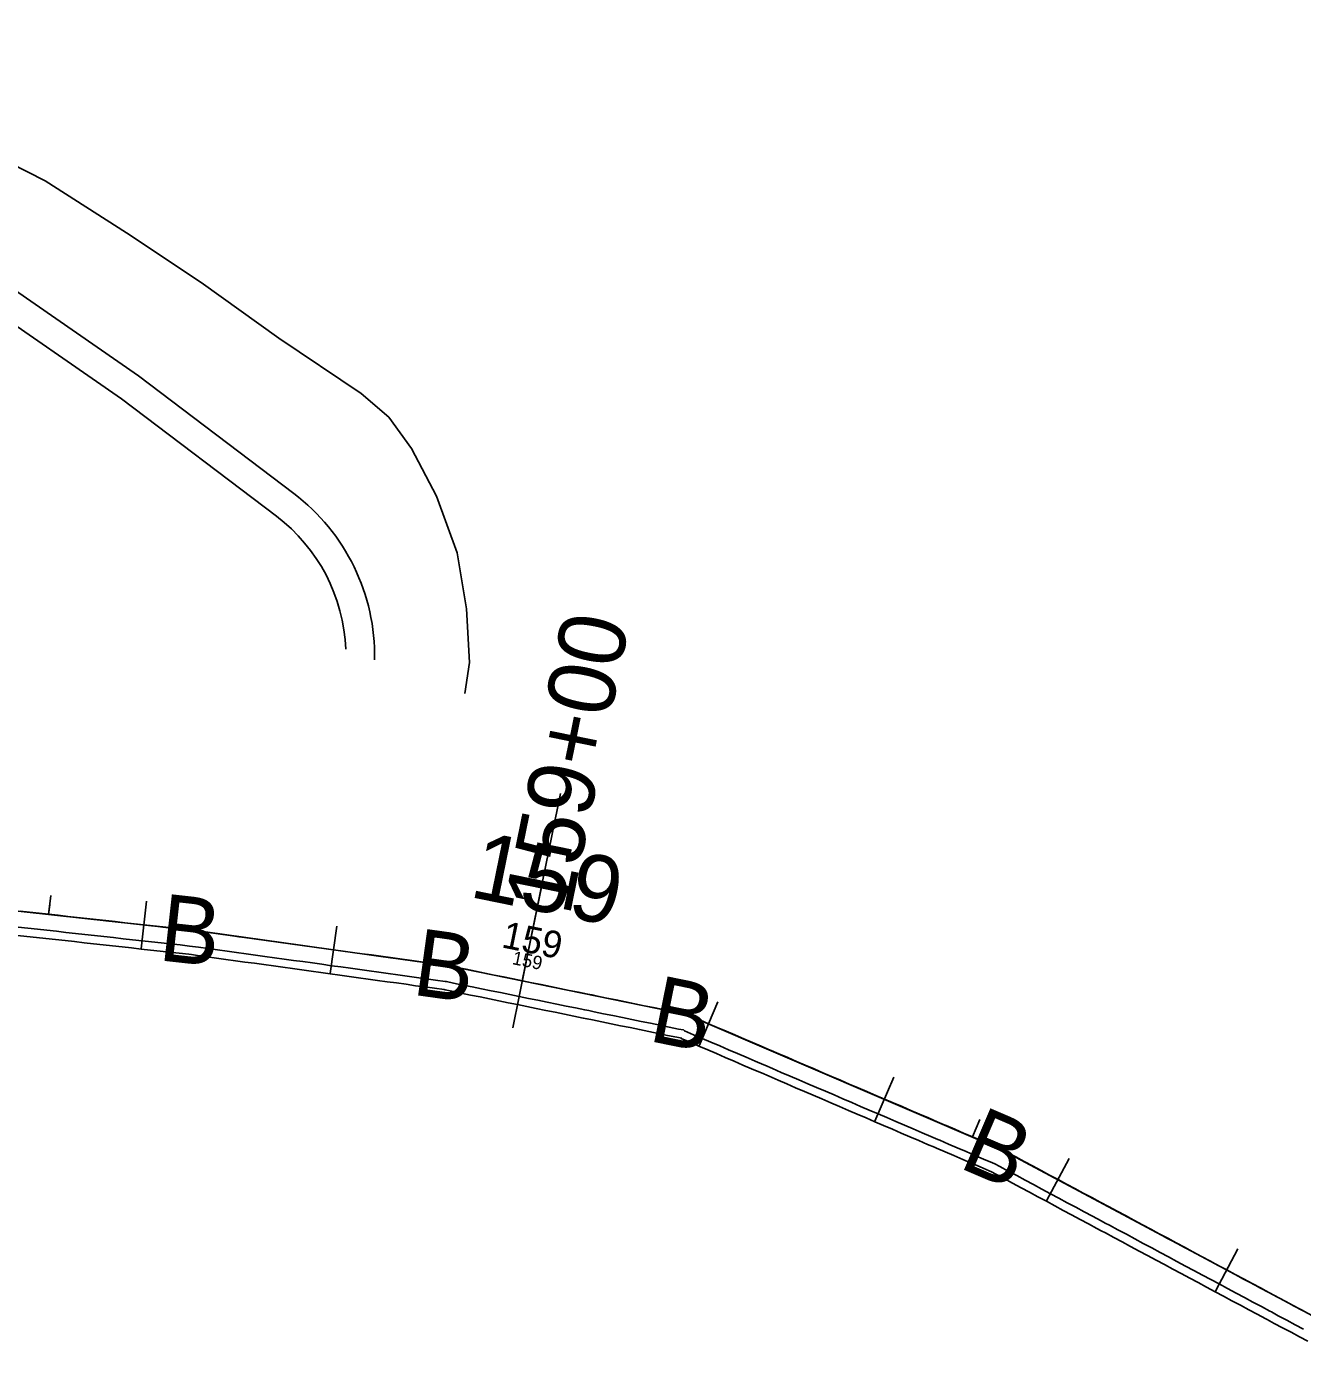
# Model space of a CAD drawing. Extents: x 1823824 to 1861612, y 706975 to 726130.
# Drawn here: x 1825799.9 to 1825933.2, y 715486.9 to 715624.8 of the extents above; entities that cross this region are included whole.
import ezdxf

# ---------------------------------------------------------------- set-up
doc = ezdxf.new("R2010")
doc.units = 0
for name, color, linetype in [('DR_X_Flood_Boundary', 7, 'Continuous'), ('GE_X_CL_10', 7, 'Continuous'), ('GE_X_CL_100', 7, 'Continuous'), ('GE_X_CL_20', 7, 'Continuous'), ('GE_X_CL_200', 7, 'Continuous'), ('GE_X_CL_50', 7, 'Continuous'), ('SC_Scratch1', 7, 'Continuous'), ('SC_Scratch3', 7, 'Continuous'), ('SC_Scratch5', 7, 'Continuous'), ('SC_Scratch6', 7, 'Continuous')]:
    doc.layers.add(name, color=color, linetype=linetype)

msp = doc.modelspace()

# ---------------------------------------------------------------- linework, layer by layer
at = {"layer": 'DR_X_Flood_Boundary'}
for p, q in [((1825794.14, 715532.96), (1825817.43, 715530.38)), ((1825817.43, 715530.38), (1825844.02, 715526.69)), ((1825844.02, 715526.69), (1825868.88, 715521.61)), ((1825868.88, 715521.61), (1825901.75, 715507.52)), ((1825901.75, 715507.52), (1825940.26, 715486.91))]:
    msp.add_line(p, q, dxfattribs=at)
at = {"layer": 'GE_X_CL_10'}
for p, q in [((1825802.23, 715532.06), (1825802.34, 715533.05)), ((1825851.72, 715525.12), (1825851.92, 715526.1)), ((1825898.74, 715508.81), (1825899.13, 715509.73))]:
    msp.add_line(p, q, dxfattribs=at)
at = {"layer": 'GE_X_CL_100'}
msp.add_line((1825851.72, 715525.12), (1825853.72, 715534.91), dxfattribs=at)
at = {"layer": 'GE_X_CL_20'}
for p, q in [((1825802.23, 715532.06), (1825802.45, 715534.05)), ((1825851.72, 715525.12), (1825852.12, 715527.08)), ((1825898.74, 715508.81), (1825899.53, 715510.65))]:
    msp.add_line(p, q, dxfattribs=at)
at = {"layer": 'GE_X_CL_200'}
msp.add_line((1825851.72, 715525.12), (1825855.72, 715544.71), dxfattribs=at)
at = {"layer": 'GE_X_CL_50'}
msp.add_line((1825851.72, 715525.12), (1825852.72, 715530.02), dxfattribs=at)
at = {"layer": 'SC_Scratch1'}
for points in [[(1825771.61, 715624.85), (1825777.97, 715621.23), (1825782.31, 715619.01), (1825786.84, 715616.63), (1825791.22, 715614.26), (1825796.17, 715611.62), (1825801.88, 715608.7)], [(1825801.88, 715608.7), (1825810.36, 715603.27), (1825818.18, 715598.09), (1825826.27, 715592.29), (1825834.88, 715586.48)], [(1825796.48, 715598.82), (1825811.61, 715588.35), (1825827.84, 715576.05)], [(1825794.94, 715596.24), (1825809.85, 715585.92), (1825826.03, 715573.66)], [(1825834.88, 715586.48), (1825837.77, 715584.01), (1825840.15, 715580.75), (1825840.15, 715580.75)], [(1825840.15, 715580.75), (1825842.76, 715575.78), (1825844.92, 715569.84), (1825845.89, 715564.01), (1825846.21, 715558.39), (1825845.73, 715555.13)]]:
    msp.add_lwpolyline(points, dxfattribs=at)
for radius, start in [(21.34, 358.9869), (18.34, 2.252)]:
    msp.add_arc((1825814.95, 715559.05), radius, start, 52.8446, dxfattribs=at)
at = {"layer": 'SC_Scratch3'}
for points in [[(1825799.25, 715532.41), (1825800.24, 715532.3), (1825801.24, 715532.19), (1825802.23, 715532.08), (1825803.22, 715531.97), (1825804.22, 715531.86), (1825805.21, 715531.75), (1825806.21, 715531.64), (1825807.2, 715531.53), (1825808.19, 715531.42), (1825809.19, 715531.31), (1825810.18, 715531.2), (1825811.18, 715531.09), (1825812.17, 715530.98), (1825813.16, 715530.87), (1825814.16, 715530.76), (1825815.15, 715530.65), (1825816.15, 715530.54), (1825817.14, 715530.43), (1825817.43, 715530.4), (1825818.13, 715530.3), (1825819.12, 715530.16), (1825820.11, 715530.03), (1825821.1, 715529.89), (1825822.09, 715529.75), (1825823.08, 715529.61), (1825824.07, 715529.48), (1825825.07, 715529.34), (1825826.06, 715529.2), (1825827.05, 715529.06)], [(1825804.22, 715531.85), (1825803.22, 715531.96), (1825802.23, 715532.07), (1825801.24, 715532.18), (1825800.24, 715532.29), (1825799.25, 715532.4)], [(1825895.8, 715510.08), (1825895.07, 715510.4), (1825894.15, 715510.79), (1825893.23, 715511.18), (1825892.31, 715511.58), (1825891.39, 715511.97), (1825890.47, 715512.37), (1825889.55, 715512.76), (1825888.63, 715513.15), (1825887.71, 715513.55), (1825886.79, 715513.94), (1825885.88, 715514.34), (1825884.96, 715514.73), (1825884.04, 715515.12), (1825883.12, 715515.52), (1825882.2, 715515.91), (1825881.28, 715516.31), (1825880.36, 715516.7), (1825879.44, 715517.09), (1825878.52, 715517.49), (1825877.71, 715517.84), (1825877.6, 715517.88), (1825876.69, 715518.28), (1825875.77, 715518.67), (1825874.85, 715519.07), (1825873.93, 715519.46), (1825873.01, 715519.85), (1825872.09, 715520.25), (1825871.17, 715520.64), (1825870.25, 715521.04), (1825869.33, 715521.43), (1825868.88, 715521.62), (1825868.38, 715521.73), (1825867.4, 715521.93), (1825866.42, 715522.13), (1825865.44, 715522.33), (1825864.46, 715522.53), (1825863.48, 715522.73), (1825862.5, 715522.93), (1825861.52, 715523.13), (1825860.54, 715523.33), (1825859.56, 715523.53), (1825858.99, 715523.64), (1825858.58, 715523.73), (1825857.6, 715523.93), (1825856.62, 715524.13), (1825855.64, 715524.33), (1825854.66, 715524.53), (1825853.68, 715524.73), (1825852.7, 715524.93), (1825851.72, 715525.13), (1825850.74, 715525.33), (1825849.76, 715525.53), (1825848.78, 715525.73), (1825847.8, 715525.93), (1825846.83, 715526.13), (1825845.85, 715526.33), (1825844.87, 715526.53), (1825844.02, 715526.7), (1825843.88, 715526.72), (1825842.89, 715526.86), (1825841.9, 715526.99), (1825840.91, 715527.13), (1825839.92, 715527.27), (1825838.93, 715527.41), (1825837.94, 715527.54), (1825836.95, 715527.68), (1825835.96, 715527.82), (1825834.97, 715527.96), (1825833.98, 715528.09), (1825832.99, 715528.23), (1825832, 715528.37), (1825831.01, 715528.51), (1825830.02, 715528.64), (1825829.03, 715528.78), (1825828.04, 715528.92), (1825827.05, 715529.06), (1825826.05, 715529.19), (1825825.06, 715529.33), (1825824.07, 715529.47), (1825823.08, 715529.61), (1825822.09, 715529.74), (1825821.1, 715529.88), (1825820.11, 715530.02), (1825819.12, 715530.16), (1825818.13, 715530.29), (1825817.43, 715530.39), (1825817.14, 715530.42), (1825816.14, 715530.53), (1825815.15, 715530.64), (1825814.16, 715530.75), (1825813.16, 715530.86), (1825812.17, 715530.97), (1825811.18, 715531.08), (1825810.18, 715531.19), (1825809.19, 715531.3), (1825808.19, 715531.41), (1825807.2, 715531.52), (1825806.21, 715531.63), (1825805.21, 715531.74), (1825804.22, 715531.85)], [(1825799.06, 715530.74), (1825800.06, 715530.63), (1825801.05, 715530.52), (1825802.05, 715530.41), (1825803.04, 715530.3), (1825804.03, 715530.19), (1825805.03, 715530.08), (1825806.02, 715529.97), (1825807.02, 715529.86), (1825808.01, 715529.75), (1825809, 715529.64), (1825810, 715529.53), (1825810.99, 715529.42), (1825811.99, 715529.31), (1825812.98, 715529.2), (1825813.97, 715529.09), (1825814.97, 715528.98), (1825815.96, 715528.87), (1825816.96, 715528.76), (1825817.25, 715528.73), (1825817.9, 715528.64), (1825818.89, 715528.5), (1825819.88, 715528.36), (1825820.87, 715528.23), (1825821.86, 715528.09), (1825822.85, 715527.95), (1825823.84, 715527.81), (1825824.83, 715527.68), (1825825.83, 715527.54), (1825826.82, 715527.4)], [(1825803.94, 715529.33), (1825802.94, 715529.43), (1825801.95, 715529.54), (1825800.96, 715529.65), (1825799.96, 715529.76), (1825798.97, 715529.86)], [(1825894.79, 715507.73), (1825894.06, 715508.04), (1825893.14, 715508.44), (1825892.22, 715508.83), (1825891.3, 715509.22), (1825890.38, 715509.62), (1825889.46, 715510.02), (1825888.54, 715510.41), (1825887.63, 715510.81), (1825886.71, 715511.2), (1825885.79, 715511.59), (1825884.87, 715511.99), (1825883.95, 715512.38), (1825883.03, 715512.78), (1825882.11, 715513.17), (1825881.19, 715513.57), (1825880.27, 715513.96), (1825879.36, 715514.36), (1825878.44, 715514.75), (1825877.52, 715515.15), (1825876.7, 715515.5), (1825876.6, 715515.54), (1825875.68, 715515.94), (1825874.76, 715516.33), (1825873.84, 715516.73), (1825872.92, 715517.12), (1825872.01, 715517.52), (1825871.09, 715517.91), (1825870.17, 715518.3), (1825869.25, 715518.7), (1825868.33, 715519.09), (1825868.37, 715519.13), (1825867.87, 715519.23), (1825866.89, 715519.43), (1825865.91, 715519.63), (1825864.93, 715519.83), (1825863.95, 715520.03), (1825862.97, 715520.24), (1825861.99, 715520.44), (1825861.01, 715520.64), (1825860.03, 715520.84), (1825859.05, 715521.04), (1825858.49, 715521.15), (1825858.08, 715521.24), (1825857.1, 715521.44), (1825856.12, 715521.64), (1825855.14, 715521.84), (1825854.16, 715522.04), (1825853.18, 715522.24), (1825852.2, 715522.44), (1825851.22, 715522.64), (1825850.24, 715522.84), (1825849.26, 715523.04), (1825848.28, 715523.24), (1825847.3, 715523.44), (1825846.32, 715523.64), (1825845.34, 715523.84), (1825844.36, 715524.04), (1825843.67, 715524.19), (1825843.54, 715524.21), (1825842.55, 715524.35), (1825841.55, 715524.49), (1825840.56, 715524.62), (1825839.57, 715524.76), (1825838.58, 715524.9), (1825837.59, 715525.03), (1825836.6, 715525.17), (1825835.61, 715525.31), (1825834.62, 715525.44), (1825833.63, 715525.58), (1825832.64, 715525.72), (1825831.65, 715525.85), (1825830.66, 715525.99), (1825829.67, 715526.13), (1825828.68, 715526.27), (1825827.69, 715526.4), (1825826.7, 715526.54), (1825825.71, 715526.68), (1825824.72, 715526.82), (1825823.72, 715526.96), (1825822.73, 715527.09), (1825821.74, 715527.23), (1825820.75, 715527.37), (1825819.76, 715527.51), (1825818.77, 715527.64), (1825817.78, 715527.78), (1825817.16, 715527.87), (1825816.86, 715527.9), (1825815.87, 715528.01), (1825814.87, 715528.12), (1825813.88, 715528.23), (1825812.88, 715528.34), (1825811.89, 715528.45), (1825810.9, 715528.56), (1825809.9, 715528.67), (1825808.91, 715528.78), (1825807.92, 715528.89), (1825806.92, 715529), (1825805.93, 715529.11), (1825804.93, 715529.22), (1825803.94, 715529.33)], [(1825827.05, 715529.06), (1825828.04, 715528.93), (1825829.03, 715528.79), (1825830.02, 715528.65), (1825831.01, 715528.51), (1825832, 715528.38), (1825832.99, 715528.24), (1825833.98, 715528.1), (1825834.97, 715527.96), (1825835.96, 715527.83), (1825836.95, 715527.69), (1825837.94, 715527.55), (1825838.93, 715527.41), (1825839.92, 715527.28), (1825840.91, 715527.14), (1825841.9, 715527), (1825842.89, 715526.86), (1825843.88, 715526.73), (1825844.02, 715526.71), (1825844.87, 715526.53), (1825845.85, 715526.33), (1825846.83, 715526.13), (1825847.81, 715525.93), (1825848.79, 715525.73), (1825849.77, 715525.53), (1825850.75, 715525.33), (1825851.73, 715525.13), (1825852.71, 715524.93), (1825853.69, 715524.73), (1825854.67, 715524.53), (1825855.64, 715524.33), (1825856.62, 715524.13), (1825857.6, 715523.93), (1825858.58, 715523.73), (1825859, 715523.65), (1825859.56, 715523.53), (1825860.54, 715523.33), (1825861.52, 715523.13), (1825862.5, 715522.93), (1825863.48, 715522.73), (1825864.46, 715522.53), (1825865.44, 715522.33), (1825866.42, 715522.13), (1825867.4, 715521.93), (1825868.38, 715521.73), (1825868.88, 715521.63), (1825869.34, 715521.44), (1825870.26, 715521.04), (1825871.17, 715520.65), (1825872.09, 715520.26), (1825873.01, 715519.86), (1825873.93, 715519.47), (1825874.85, 715519.07), (1825875.77, 715518.68), (1825876.69, 715518.29), (1825877.61, 715517.89), (1825877.71, 715517.85), (1825878.53, 715517.5), (1825879.45, 715517.1), (1825880.36, 715516.71), (1825881.28, 715516.31), (1825882.2, 715515.92), (1825883.12, 715515.53), (1825884.04, 715515.13), (1825884.96, 715514.74), (1825885.88, 715514.34), (1825886.8, 715513.95), (1825887.72, 715513.56), (1825888.64, 715513.16), (1825889.56, 715512.77), (1825890.47, 715512.37), (1825891.39, 715511.98), (1825892.31, 715511.59), (1825893.23, 715511.19), (1825894.15, 715510.8), (1825895.07, 715510.4), (1825895.81, 715510.09), (1825895.99, 715510.01), (1825896.91, 715509.62), (1825897.83, 715509.22), (1825898.75, 715508.83), (1825899.67, 715508.43), (1825900.58, 715508.04), (1825901.5, 715507.64), (1825901.76, 715507.53), (1825902.4, 715507.19), (1825903.28, 715506.72), (1825904.16, 715506.25), (1825905.04, 715505.78), (1825905.92, 715505.31), (1825906.81, 715504.83), (1825907.69, 715504.36), (1825908.57, 715503.89), (1825909.45, 715503.42), (1825910.33, 715502.95), (1825911.21, 715502.48), (1825912.1, 715502), (1825912.98, 715501.53), (1825913.41, 715501.3), (1825913.86, 715501.06), (1825914.74, 715500.59)], [(1825826.82, 715527.4), (1825827.81, 715527.26), (1825828.8, 715527.13), (1825829.79, 715526.99), (1825830.78, 715526.85), (1825831.77, 715526.71), (1825832.76, 715526.58), (1825833.75, 715526.44), (1825834.74, 715526.3), (1825835.73, 715526.16), (1825836.72, 715526.03), (1825837.71, 715525.89), (1825838.7, 715525.75), (1825839.69, 715525.61), (1825840.68, 715525.48), (1825841.67, 715525.34), (1825842.66, 715525.2), (1825843.65, 715525.06), (1825843.79, 715525.05), (1825844.53, 715524.89), (1825845.51, 715524.69), (1825846.49, 715524.49), (1825847.47, 715524.29), (1825848.45, 715524.09), (1825849.43, 715523.89), (1825850.41, 715523.69), (1825851.39, 715523.49), (1825852.37, 715523.29), (1825853.35, 715523.09), (1825854.33, 715522.89), (1825855.31, 715522.69), (1825856.29, 715522.49), (1825857.27, 715522.29), (1825858.25, 715522.09), (1825858.66, 715522.01), (1825859.23, 715521.89), (1825860.21, 715521.69), (1825861.19, 715521.49), (1825862.17, 715521.29), (1825863.15, 715521.09), (1825864.13, 715520.89), (1825865.11, 715520.69), (1825866.09, 715520.49), (1825867.07, 715520.29), (1825868.05, 715520.09), (1825868.55, 715519.99), (1825868.67, 715519.9), (1825869.59, 715519.5), (1825870.51, 715519.11), (1825871.43, 715518.71), (1825872.35, 715518.32), (1825873.27, 715517.92), (1825874.19, 715517.53), (1825875.11, 715517.14), (1825876.03, 715516.74), (1825876.95, 715516.35), (1825877.05, 715516.3), (1825877.87, 715515.95), (1825878.78, 715515.56), (1825879.7, 715515.17), (1825880.62, 715514.77), (1825881.54, 715514.38), (1825882.46, 715513.98), (1825883.38, 715513.59), (1825884.3, 715513.2), (1825885.22, 715512.8), (1825886.14, 715512.41), (1825887.06, 715512.01), (1825887.97, 715511.62), (1825888.89, 715511.23), (1825889.81, 715510.83), (1825890.73, 715510.44), (1825891.65, 715510.04), (1825892.57, 715509.65), (1825893.49, 715509.25), (1825894.41, 715508.86), (1825895.14, 715508.55), (1825895.33, 715508.47), (1825896.25, 715508.07), (1825897.17, 715507.68), (1825898.08, 715507.28), (1825899, 715506.89), (1825899.92, 715506.5), (1825900.84, 715506.1), (1825901.1, 715505.99), (1825901.6, 715505.71), (1825902.49, 715505.24), (1825903.37, 715504.77), (1825904.25, 715504.3), (1825905.13, 715503.83), (1825906.01, 715503.35), (1825906.89, 715502.88), (1825907.78, 715502.41), (1825908.66, 715501.94), (1825909.54, 715501.47), (1825910.42, 715501), (1825911.3, 715500.52), (1825912.19, 715500.05), (1825912.62, 715499.82), (1825913.07, 715499.58), (1825913.95, 715499.11)], [(1825933.25, 715490.67), (1825932.37, 715491.14), (1825931.49, 715491.62), (1825930.77, 715492), (1825930.61, 715492.09), (1825929.72, 715492.56), (1825928.84, 715493.03), (1825927.96, 715493.5), (1825927.08, 715493.97), (1825926.2, 715494.45), (1825925.32, 715494.92), (1825924.43, 715495.39), (1825923.55, 715495.86), (1825922.67, 715496.33), (1825921.79, 715496.81), (1825920.91, 715497.28), (1825920.03, 715497.75), (1825919.14, 715498.22), (1825918.26, 715498.69), (1825917.38, 715499.16), (1825916.5, 715499.64), (1825915.62, 715500.11), (1825914.74, 715500.58), (1825913.85, 715501.05), (1825913.41, 715501.29), (1825912.97, 715501.52), (1825912.09, 715502), (1825911.21, 715502.47), (1825910.33, 715502.94), (1825909.45, 715503.41), (1825908.56, 715503.88), (1825907.68, 715504.36), (1825906.8, 715504.83), (1825905.92, 715505.3), (1825905.04, 715505.77), (1825904.16, 715506.24), (1825903.27, 715506.71), (1825902.39, 715507.19), (1825901.76, 715507.53), (1825901.5, 715507.64), (1825900.58, 715508.03), (1825899.66, 715508.42), (1825898.74, 715508.82), (1825897.82, 715509.21), (1825896.9, 715509.61), (1825895.99, 715510), (1825895.8, 715510.08)], [(1825933.8, 715487.46), (1825932.92, 715487.93), (1825932.04, 715488.4), (1825931.15, 715488.87), (1825930.27, 715489.34), (1825929.55, 715489.73), (1825929.39, 715489.81), (1825928.51, 715490.29), (1825927.63, 715490.76), (1825926.75, 715491.23), (1825925.86, 715491.7), (1825924.98, 715492.17), (1825924.1, 715492.64), (1825923.22, 715493.12), (1825922.34, 715493.59), (1825921.45, 715494.06), (1825920.57, 715494.53), (1825919.69, 715495), (1825918.81, 715495.47), (1825917.93, 715495.95), (1825917.05, 715496.42), (1825916.17, 715496.89), (1825915.28, 715497.37), (1825914.4, 715497.84), (1825913.52, 715498.31), (1825912.64, 715498.78), (1825912.19, 715499.02), (1825911.76, 715499.25), (1825910.88, 715499.73), (1825910, 715500.2), (1825909.11, 715500.67), (1825908.23, 715501.14), (1825907.35, 715501.62), (1825906.47, 715502.09), (1825905.59, 715502.56), (1825904.71, 715503.04), (1825903.83, 715503.51), (1825902.95, 715503.98), (1825902.07, 715504.46), (1825901.18, 715504.93), (1825900.75, 715505.17), (1825900.49, 715505.28), (1825899.57, 715505.68), (1825898.65, 715506.07), (1825897.73, 715506.46), (1825896.81, 715506.86), (1825895.9, 715507.25), (1825894.98, 715507.65), (1825894.79, 715507.73)], [(1825914.74, 715500.59), (1825915.62, 715500.12), (1825916.5, 715499.64), (1825917.39, 715499.17), (1825918.27, 715498.7), (1825919.15, 715498.23), (1825920.03, 715497.76), (1825920.91, 715497.29), (1825921.79, 715496.81), (1825922.68, 715496.34), (1825923.56, 715495.87), (1825924.44, 715495.4), (1825925.32, 715494.93), (1825926.2, 715494.45), (1825927.08, 715493.98), (1825927.97, 715493.51), (1825928.85, 715493.04), (1825929.73, 715492.57), (1825930.61, 715492.09), (1825930.77, 715492.01), (1825931.49, 715491.62), (1825932.37, 715491.15), (1825933.26, 715490.68)], [(1825913.95, 715499.11), (1825914.83, 715498.64), (1825915.71, 715498.16), (1825916.59, 715497.69), (1825917.48, 715497.22), (1825918.36, 715496.75), (1825919.24, 715496.28), (1825920.12, 715495.8), (1825921, 715495.33), (1825921.88, 715494.86), (1825922.77, 715494.39), (1825923.65, 715493.92), (1825924.53, 715493.45), (1825925.41, 715492.97), (1825926.29, 715492.5), (1825927.17, 715492.03), (1825928.06, 715491.56), (1825928.94, 715491.09), (1825929.82, 715490.61), (1825929.98, 715490.53), (1825930.7, 715490.14), (1825931.58, 715489.67), (1825932.46, 715489.2), (1825933.35, 715488.73)]]:
    msp.add_lwpolyline(points, dxfattribs=at)
at = {"layer": 'SC_Scratch5'}
for points in [[(1825812.44, 715533.45), (1825811.89, 715528.48)], [(1825832.34, 715530.83), (1825831.65, 715525.88)], [(1825852.72, 715530.02), (1825850.72, 715520.22)], [(1825872.15, 715522.93), (1825870.18, 715518.33)], [(1825890.53, 715515.05), (1825888.56, 715510.45)], [(1825908.86, 715506.55), (1825906.5, 715502.14)], [(1825926.49, 715497.11), (1825924.13, 715492.7)]]:
    msp.add_lwpolyline(points, dxfattribs=at)

# ---------------------------------------------------------------- texts
at = {"layer": 'GE_X_CL_10'}
msp.add_text('159', height=1.4, rotation=348.4616, dxfattribs=at).set_placement((1825850.59, 715526.88))
at = {"layer": 'GE_X_CL_20'}
msp.add_text('159', height=2.8, rotation=348.4616, dxfattribs=at).set_placement((1825849.45, 715528.64))
at = {"layer": 'GE_X_CL_50'}
msp.add_text('159', height=7, rotation=348.4616, dxfattribs=at).set_placement((1825846.04, 715533.93))
at = {"layer": 'SC_Scratch5'}
msp.add_text('159+00', height=7, rotation=78.4616, dxfattribs=at).set_placement((1825856.65, 715531.77))
at = {"layer": 'SC_Scratch6'}
for rotation, p in [(353.6898, (1825813.57, 715527.29)), (352.0972, (1825840.07, 715523.7)), (348.4616, (1825864.75, 715518.88)), (336.7901, (1825897.16, 715505.68))]:
    msp.add_text('B', height=7, rotation=rotation, dxfattribs=at).set_placement(p)

doc.saveas('drawing.dxf')
